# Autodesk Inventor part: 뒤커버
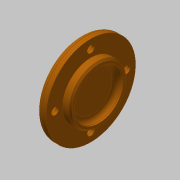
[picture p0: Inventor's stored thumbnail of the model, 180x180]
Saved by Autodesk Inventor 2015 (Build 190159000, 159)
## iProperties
Created: 2019-06
Part Number: 뒤커버
Material: 알루미늄 6061
Document SubType Name: Modeling
Designer: mduedu
Density: 1 g/cm^3
Appearance: 주황색
Author: mduedu
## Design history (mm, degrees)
sketch "스케치1"
  geometry: L1 (0, 0)-(-5, 0); L2 (-5, 0)-(-5, 17.5); L3 (-5, 17.5)-(0, 17.5); L4 (0, 17.5)-(0, 0); L5 (-5, 0)-(-11, 0); L6 (-11, 0)-(-11, 27.5); L7 (-11, 27.5)-(-5, 27.5); L8 (-5, 27.5)-(-5, 0)
  constraints: 16 end point, 4 parallel, 2 horizontal, 2 perpendicular
  dimensions: "d0" = 11 distance between parallel lines of L4 L6; "d2" = 5 distance of L2.end L3.end; "d3" = 55 diameter of L7 L5; "d4" = 35 diameter of L3 L1
revolve "회전1" sketch "스케치1" stored, may be unused: angle "d5" = 90 deg
sketch "스케치2"
  geometry: C1 r 15 at (0, 0); 1 further point
  constraints: 1 centre point, 1 coincident
  dimensions: "d6" = 30 diameter of C1
extrude "돌출1" cut sketch "스케치2" distance "d7" = 4; taper "d8" = 0 deg
fillet "모깎기1" dims "d9" = 3
fillet "모깎기2" dims "d10" = 3
chamfer "모따기1" distance "d11" = 1; stored, may be unused: second distance "d12" = 2, angle "d13" = 45 deg
sketch "스케치3" dims "d14" = 44
  geometry: 3 further points
  constraints: 2 vertical alignment, 1 coincident, 2 other
hole "구멍1" sketch "스케치3" at (0, 22) diameter "d15" = 4.5; stored, may be unused: countersink angle "d19" = 90 deg, drill point angle "d21" = 118 deg; dims "d16" = 6, "d17" = 8, "d18" = 4.4, "d20" = 8
node "솔리드1"
pattern_circular "원형 패턴1" dims angle "d23" = 360 deg
